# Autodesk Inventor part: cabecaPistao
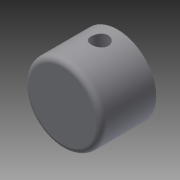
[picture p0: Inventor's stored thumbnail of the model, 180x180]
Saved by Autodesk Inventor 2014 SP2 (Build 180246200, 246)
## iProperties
Created: 2016-04
Part Number: cabecaPistao
Material: Genérico
Document SubType Name: Modeling
Designer: Celiberto
Density: 1 g/cm^3
Appearance: Padrão
Mass: 0.751048 g
Surface Area: 11.568 cm^2
Volume: 0.751048 cm^3
Author: Celiberto
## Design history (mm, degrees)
sketch "Esboço1"
  geometry: C1 r 7 at (0, 0); 1 further point
  constraints: 1 centre point, 1 coincident
  dimensions: "d0" = 14 diameter of C1
extrude "Extrusão1" new body sketch "Esboço1" distance "d1" = 10; taper "d2" = 0 deg
sketch "Esboço2"
  geometry: C1 r 7 at (0, 0) reference; C2 r 6.35 at (0, 0)
  constraints: 1 centre point, 1 coincident
  dimensions: "d3" = 12.7 diameter of C2
extrude "Extrusão2" cut sketch "Esboço2" distance "d4" = 7.5; taper "d5" = 0 deg
node "Plano de trabalho1"
sketch "Esboço3"
  geometry: L1 (-6.35, 10)-(6.35, 10) reference; L2 (-2.2, 6.8)-(-2.2, 2.5); L3 (2.2, 6.8)-(2.2, 2.5); L4 (-6.35, 2.5)-(6.35, 2.5) reference; A1 r 2.2 centre (0, 6.8) between (2.2, 6.8) and (-2.2, 6.8); 1 further point
  constraints: 4 end point, 2 point on circle, 2 point on line, 2 tangent, 1 centre point, 1 parallel, 1 perpendicular
  dimensions: "d7" = 4.4 diameter of A1; "d8" = 3.2 distance from line of L1 A1.centre
extrude "Extrusão3" join sketch "Esboço3" stored distance "d10" = 3.25; taper "d11" = 0 deg
mirror "Simetria1"
sketch "Esboço4"
  geometry: C1 r 1.5 at (0, 0); A1 r 2.2 centre (0, 0) between (2.2, 0) and (-2.2, 0) reference; 1 further point
  constraints: 1 centre point, 1 coincident
  dimensions: "d12" = 3 diameter of C1
extrude "Extrusão4" cut sketch "Esboço4" stored distance "d13" = 26.25; taper "d14" = 0 deg
fillet "Arredondamento1" dims "d15" = 0.5
fillet "Arredondamento2" dims "d16" = 0.1
fillet "Arredondamento3" dims "d17" = 0.5
fillet "Arredondamento4" dims "d18" = 0.5
fillet "Arredondamento5" dims "d19" = 1
node "Sólido1"
other parameters: "d6" = 1.7, "d9" = 3.25
